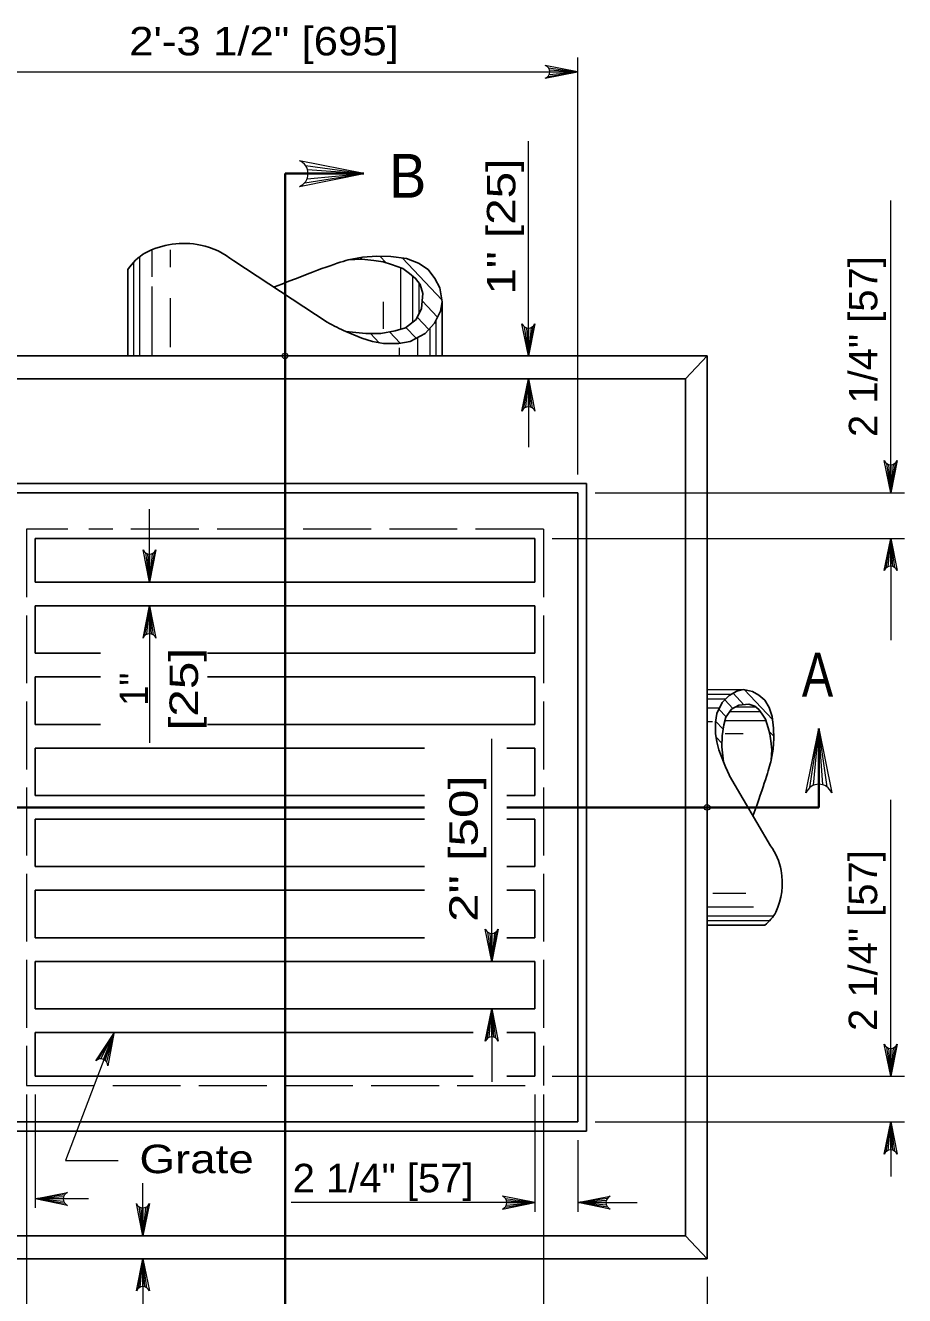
# Model space of a CAD drawing. Extents: x -410.5 to -376.5, y 1617.6 to 1661.6.
# Drawn here: x -393.89 to -389.07, y 1621.21 to 1628.17 of the extents above; entities that cross this region are included whole.
import ezdxf
from ezdxf.enums import TextEntityAlignment as Align

# ---------------------------------------------------------------- set-up
doc = ezdxf.new("R2010")
doc.units = 0
doc.header["$LTSCALE"] = 0.062
doc.header["$PDMODE"] = 32
doc.header["$PDSIZE"] = 0.031
doc.linetypes.add('LONG_DASHED', pattern=[7.5, 6, -1.5])
doc.layers.add('1', color=7, linetype='Continuous', lineweight=13)

msp = doc.modelspace()

# ---------------------------------------------------------------- linework, layer by layer
at = {"layer": '1'}
for p, q in [((-391.02133, 1627.94108), (-390.86108, 1627.91867)), ((-390.85967, 1625.71183), (-390.85967, 1627.99733)), ((-394.07075, 1627.91867), (-392.13725, 1627.91867)), ((-392.13725, 1627.91867), (-390.86108, 1627.91867)), ((-391.02325, 1627.89392), (-390.86108, 1627.91867)), ((-391.01708, 1627.90425), (-390.86108, 1627.91867)), ((-391.01592, 1627.93), (-390.86108, 1627.91867)), ((-391.01425, 1627.91867), (-390.86108, 1627.91867)), ((-391.13075, 1626.3615), (-391.13075, 1627.538)), ((-392.35233, 1627.40575), (-392.03183, 1627.36092)), ((-392.3415, 1627.38358), (-392.03183, 1627.36092)), ((-392.35617, 1627.31133), (-392.03183, 1627.36092)), ((-392.34383, 1627.33217), (-392.03183, 1627.36092)), ((-392.33817, 1627.36092), (-392.03183, 1627.36092)), ((-389.14558, 1625.61192), (-389.14558, 1627.21383)), ((-393.2595, 1626.3615), (-393.2595, 1626.90692)), ((-393.19267, 1626.79592), (-393.19267, 1626.94417)), ((-393.0925, 1626.84867), (-393.0925, 1626.94417)), ((-392.08983, 1626.8895), (-392.09308, 1626.89292)), ((-392.04525, 1626.89225), (-392.05358, 1626.90092)), ((-392.04175, 1626.89217), (-392.05067, 1626.90158)), ((-391.90942, 1626.87167), (-391.94433, 1626.90892)), ((-391.60458, 1626.66892), (-391.82083, 1626.89808)), ((-393.29283, 1626.3615), (-393.29283, 1626.87667)), ((-391.83, 1626.50817), (-391.83, 1626.84417)), ((-391.76325, 1626.54892), (-391.76325, 1626.79842)), ((-391.72983, 1626.59508), (-391.72983, 1626.76183)), ((-393.19267, 1626.3615), (-393.19267, 1626.74308)), ((-393.0925, 1626.40983), (-393.0925, 1626.67908)), ((-391.92458, 1626.51033), (-391.92458, 1626.65842)), ((-391.629, 1626.57508), (-391.71325, 1626.66425)), ((-391.67717, 1626.50608), (-391.741, 1626.57358)), ((-391.63608, 1626.3615), (-391.63608, 1626.56067)), ((-392.12725, 1626.4935), (-392.12867, 1626.49525)), ((-392.113, 1626.48775), (-392.11917, 1626.49417)), ((-391.949, 1626.43408), (-391.9965, 1626.48433)), ((-391.833, 1626.43125), (-391.892, 1626.49367)), ((-391.74558, 1626.4585), (-391.80183, 1626.51817)), ((-391.6695, 1626.3615), (-391.6695, 1626.51467)), ((-391.15317, 1626.52175), (-391.13075, 1626.3615)), ((-391.14208, 1626.51633), (-391.13075, 1626.3615)), ((-391.106, 1626.52367), (-391.13075, 1626.3615)), ((-391.11633, 1626.5175), (-391.13075, 1626.3615)), ((-391.13075, 1626.51467), (-391.13075, 1626.3615)), ((-391.83642, 1626.3615), (-391.83642, 1626.40692)), ((-391.73625, 1626.3615), (-391.73625, 1626.46342)), ((-391.1555, 1626.07442), (-391.13075, 1626.23658)), ((-391.14517, 1626.08058), (-391.13075, 1626.23658)), ((-391.13075, 1626.23658), (-391.13075, 1625.861)), ((-391.13075, 1626.08342), (-391.13075, 1626.23658)), ((-391.11942, 1626.08175), (-391.13075, 1626.23658)), ((-391.10833, 1626.07633), (-391.13075, 1626.23658)), ((-389.168, 1625.77217), (-389.14558, 1625.61192)), ((-389.15692, 1625.76675), (-389.14558, 1625.61192)), ((-389.12075, 1625.77408), (-389.14558, 1625.61192)), ((-389.13117, 1625.76792), (-389.14558, 1625.61192)), ((-389.14558, 1625.76508), (-389.14558, 1625.61192)), ((-390.76525, 1625.61192), (-389.06933, 1625.61192)), ((-393.207, 1625.12225), (-393.207, 1625.522)), ((-391.00125, 1625.36208), (-389.06933, 1625.36208)), ((-389.17033, 1625.19992), (-389.14558, 1625.36208)), ((-389.16, 1625.20608), (-389.14558, 1625.36208)), ((-389.14558, 1625.36208), (-389.14558, 1624.8035)), ((-389.14558, 1625.20892), (-389.14558, 1625.36208)), ((-389.13425, 1625.20725), (-389.14558, 1625.36208)), ((-389.12317, 1625.20183), (-389.14558, 1625.36208)), ((-393.22942, 1625.28242), (-393.207, 1625.12225)), ((-393.21833, 1625.277), (-393.207, 1625.12225)), ((-393.18225, 1625.28433), (-393.207, 1625.12225)), ((-393.19267, 1625.27825), (-393.207, 1625.12225)), ((-393.207, 1625.27542), (-393.207, 1625.12225)), ((-393.23183, 1624.83017), (-393.207, 1624.99225)), ((-393.22142, 1624.83633), (-393.207, 1624.99225)), ((-393.207, 1624.99225), (-393.207, 1624.24208)), ((-393.207, 1624.83917), (-393.207, 1624.99225)), ((-393.19567, 1624.8375), (-393.207, 1624.99225)), ((-393.18458, 1624.83208), (-393.207, 1624.99225)), ((-390.15167, 1624.533), (-389.95292, 1624.533)), ((-389.94633, 1624.53167), (-389.79333, 1624.36975)), ((-390.15167, 1624.508), (-390.01867, 1624.508)), ((-390.15167, 1624.483), (-390.04942, 1624.483)), ((-390.05517, 1624.47725), (-390.01008, 1624.4295)), ((-390.00908, 1624.51333), (-389.9495, 1624.45025)), ((-390.15167, 1624.433), (-390.08358, 1624.433)), ((-390.08683, 1624.426), (-390.047, 1624.38392)), ((-390.0265, 1624.41283), (-389.85992, 1624.41283)), ((-389.99558, 1624.43783), (-389.88425, 1624.43783)), ((-390.15167, 1624.35808), (-390.12142, 1624.35808)), ((-390.10508, 1624.36058), (-390.06342, 1624.31642)), ((-390.05375, 1624.36292), (-389.82933, 1624.36292)), ((-389.58875, 1623.99633), (-389.53917, 1624.32058)), ((-389.568, 1624.00858), (-389.53917, 1624.32058)), ((-389.53917, 1624.01425), (-389.53917, 1624.32058)), ((-389.5165, 1624.011), (-389.53917, 1624.32058)), ((-389.49433, 1624.00008), (-389.53917, 1624.32058)), ((-391.33167, 1623.04342), (-391.33167, 1624.26375)), ((-390.10317, 1624.27375), (-390.06958, 1624.23825)), ((-390.05225, 1624.29208), (-389.95333, 1624.29208)), ((-389.81092, 1624.30342), (-389.78608, 1624.27725)), ((-389.79725, 1624.20433), (-389.791, 1624.19767)), ((-389.79717, 1624.20175), (-389.79133, 1624.1955)), ((-390.06733, 1624.151), (-390.06308, 1624.14642)), ((-390.0635, 1624.14033), (-390.06242, 1624.13925)), ((-389.799, 1624.16833), (-389.79675, 1624.16592)), ((-389.14558, 1622.41375), (-389.14558, 1623.92875)), ((-390.11942, 1623.41775), (-389.93958, 1623.41775)), ((-390.059, 1623.41775), (-389.99525, 1623.41775)), ((-390.15167, 1623.34283), (-389.89675, 1623.34283)), ((-390.09417, 1623.34283), (-389.99525, 1623.34283)), ((-390.15167, 1623.29283), (-389.78733, 1623.29283)), ((-391.35408, 1623.20367), (-391.33167, 1623.04342)), ((-391.30692, 1623.20558), (-391.33167, 1623.04342)), ((-390.15167, 1623.26783), (-389.80758, 1623.26783)), ((-391.343, 1623.19825), (-391.33167, 1623.04342)), ((-391.31725, 1623.19942), (-391.33167, 1623.04342)), ((-391.33167, 1623.19658), (-391.33167, 1623.04342)), ((-391.35642, 1622.62142), (-391.33167, 1622.78358)), ((-391.34608, 1622.62758), (-391.33167, 1622.78358)), ((-391.33167, 1622.78358), (-391.33167, 1622.38375)), ((-391.33167, 1622.63042), (-391.33167, 1622.78358)), ((-391.32033, 1622.62875), (-391.33167, 1622.78358)), ((-391.30925, 1622.62333), (-391.33167, 1622.78358)), ((-393.48625, 1622.50792), (-393.402, 1622.64867)), ((-393.47425, 1622.50967), (-393.402, 1622.64867)), ((-393.45992, 1622.50683), (-393.402, 1622.64867)), ((-393.45, 1622.501), (-393.402, 1622.64867)), ((-393.44183, 1622.49183), (-393.402, 1622.64867)), ((-389.168, 1622.574), (-389.14558, 1622.41375)), ((-389.12075, 1622.57592), (-389.14558, 1622.41375)), ((-389.15692, 1622.56858), (-389.14558, 1622.41375)), ((-389.13117, 1622.56975), (-389.14558, 1622.41375)), ((-389.14558, 1622.56692), (-389.14558, 1622.41375)), ((-391.00125, 1622.41375), (-389.06933, 1622.41375)), ((-393.8805, 1622.31383), (-393.8805, 1620.696)), ((-393.83325, 1622.31383), (-393.83325, 1621.69217)), ((-391.09567, 1622.31383), (-391.09567, 1621.67183)), ((-391.0485, 1622.31383), (-391.0485, 1620.696)), ((-390.76525, 1622.164), (-389.06933, 1622.164)), ((-389.17033, 1622.00183), (-389.14558, 1622.164)), ((-389.16, 1622.008), (-389.14558, 1622.164)), ((-389.14558, 1622.164), (-389.14558, 1621.86558)), ((-389.14558, 1622.01083), (-389.14558, 1622.164)), ((-389.13425, 1622.00917), (-389.14558, 1622.164)), ((-389.12317, 1622.00375), (-389.14558, 1622.164)), ((-390.85967, 1622.06408), (-390.85967, 1621.67192)), ((-393.24325, 1621.53925), (-393.24325, 1621.82733)), ((-393.673, 1621.7645), (-393.83325, 1621.74208)), ((-393.67842, 1621.75342), (-393.83325, 1621.74208)), ((-393.542, 1621.74208), (-393.83325, 1621.74208)), ((-393.68008, 1621.74208), (-393.83325, 1621.74208)), ((-393.67725, 1621.72767), (-393.83325, 1621.74208)), ((-393.67117, 1621.71733), (-393.83325, 1621.74208)), ((-391.25592, 1621.74417), (-391.09567, 1621.72175)), ((-390.69942, 1621.74425), (-390.85967, 1621.72183)), ((-393.26567, 1621.6995), (-393.24325, 1621.53925)), ((-393.25458, 1621.69408), (-393.24325, 1621.53925)), ((-393.2185, 1621.70142), (-393.24325, 1621.53925)), ((-393.22883, 1621.69525), (-393.24325, 1621.53925)), ((-393.24325, 1621.69242), (-393.24325, 1621.53925)), ((-391.09567, 1621.72175), (-392.43067, 1621.72175)), ((-391.25783, 1621.697), (-391.09567, 1621.72175)), ((-391.25167, 1621.70733), (-391.09567, 1621.72175)), ((-391.2505, 1621.73308), (-391.09567, 1621.72175)), ((-391.24883, 1621.72175), (-391.09567, 1621.72175)), ((-390.70483, 1621.73317), (-390.85967, 1621.72183)), ((-390.85967, 1621.72183), (-390.53558, 1621.72183)), ((-390.7065, 1621.72183), (-390.85967, 1621.72183)), ((-390.70367, 1621.70742), (-390.85967, 1621.72183)), ((-390.6975, 1621.69708), (-390.85967, 1621.72183)), ((-393.26808, 1621.25225), (-393.24325, 1621.41433)), ((-393.25767, 1621.25833), (-393.24325, 1621.41433)), ((-393.24325, 1621.41433), (-393.24325, 1620.30867)), ((-393.24325, 1621.26117), (-393.24325, 1621.41433)), ((-393.23192, 1621.2595), (-393.24325, 1621.41433)), ((-393.22083, 1621.25408), (-393.24325, 1621.41433)), ((-390.15167, 1621.31492), (-390.15167, 1620.696))]:
    msp.add_line(p, q, dxfattribs=at)
at = {"layer": '1', "lineweight": 35}
for p, q in [((-392.4645, 1627.36092), (-392.03183, 1627.36092)), ((-392.4645, 1626.28775), (-392.4645, 1627.36092)), ((-392.4645, 1620.41492), (-392.4645, 1626.28775)), ((-389.53917, 1623.88792), (-389.53917, 1624.32058)), ((-395.3405, 1623.88792), (-391.70058, 1623.88792)), ((-391.24825, 1623.88792), (-389.53917, 1623.88792))]:
    msp.add_line(p, q, dxfattribs=at)
at = {"layer": '1', "lineweight": 25}
for p, q in [((-393.32617, 1626.3615), (-393.32617, 1626.83475)), ((-392.234, 1626.54667), (-392.74575, 1626.88208)), ((-391.60275, 1626.3615), (-391.60275, 1626.65917)), ((-390.15167, 1626.3615), (-390.26967, 1626.23658)), ((-390.15167, 1626.3615), (-390.15167, 1625.24567)), ((-394.65925, 1626.23658), (-390.26967, 1626.23658)), ((-390.85967, 1625.61192), (-394.06925, 1625.61192)), ((-390.85967, 1622.164), (-390.85967, 1625.61192)), ((-393.83325, 1625.36208), (-393.83325, 1625.12225)), ((-391.09567, 1625.36208), (-391.09567, 1625.12225)), ((-390.15167, 1625.28292), (-390.15167, 1621.41433)), ((-393.83325, 1625.12225), (-391.09567, 1625.12225)), ((-393.83325, 1624.99225), (-391.09567, 1624.99225)), ((-393.83325, 1624.99225), (-393.83325, 1624.73242)), ((-391.09567, 1624.99225), (-391.09567, 1624.73242)), ((-393.83325, 1624.73242), (-393.47633, 1624.73242)), ((-392.88867, 1624.73242), (-391.09567, 1624.73242)), ((-393.83325, 1624.6025), (-393.83325, 1624.34267)), ((-393.83325, 1624.6025), (-393.47633, 1624.6025)), ((-392.88867, 1624.6025), (-391.09567, 1624.6025)), ((-391.09567, 1624.6025), (-391.09567, 1624.34267)), ((-393.83325, 1624.34267), (-393.47633, 1624.34267)), ((-392.88867, 1624.34267), (-391.09567, 1624.34267)), ((-393.83325, 1624.21275), (-393.83325, 1623.95292)), ((-393.83325, 1624.21275), (-391.70058, 1624.21275)), ((-391.24825, 1624.21275), (-391.09567, 1624.21275)), ((-391.09567, 1624.21275), (-391.09567, 1623.95292)), ((-390.028, 1624.0605), (-389.804, 1623.67742)), ((-393.83325, 1623.95292), (-391.70058, 1623.95292)), ((-391.24825, 1623.95292), (-391.09567, 1623.95292)), ((-393.83325, 1623.56308), (-393.83325, 1623.823)), ((-393.83325, 1623.823), (-391.70058, 1623.823)), ((-391.24825, 1623.823), (-391.09567, 1623.823)), ((-391.09567, 1623.56308), (-391.09567, 1623.823)), ((-393.83325, 1623.56308), (-391.70058, 1623.56308)), ((-391.24825, 1623.56308), (-391.09567, 1623.56308)), ((-393.83325, 1623.43317), (-393.83325, 1623.17333)), ((-393.83325, 1623.43317), (-391.70058, 1623.43317)), ((-391.24825, 1623.43317), (-391.09567, 1623.43317)), ((-391.09567, 1623.17333), (-391.09567, 1623.43317)), ((-390.15167, 1623.24292), (-389.83567, 1623.24292)), ((-393.83325, 1623.17333), (-391.70058, 1623.17333)), ((-391.24825, 1623.17333), (-391.09567, 1623.17333)), ((-393.83325, 1623.04342), (-391.09567, 1623.04342)), ((-393.83325, 1623.04342), (-393.83325, 1622.78358)), ((-391.09567, 1622.78358), (-391.09567, 1623.04342)), ((-393.83325, 1622.78358), (-391.09567, 1622.78358)), ((-393.83325, 1622.65367), (-393.83325, 1622.41375)), ((-393.83325, 1622.65367), (-391.43333, 1622.65367)), ((-391.24825, 1622.65367), (-391.09567, 1622.65367)), ((-391.09567, 1622.41383), (-391.09567, 1622.65367)), ((-393.83325, 1622.41375), (-391.43333, 1622.41383)), ((-391.24825, 1622.41383), (-391.09567, 1622.41383)), ((-394.06925, 1622.16392), (-390.85967, 1622.164)), ((-394.65925, 1621.53925), (-390.26967, 1621.53933)), ((-390.15167, 1621.41433), (-390.26967, 1621.53933)), ((-394.77725, 1621.41433), (-390.15167, 1621.41442))]:
    msp.add_line(p, q, dxfattribs=at)
at = {"layer": '1', "linetype": 'LONG_DASHED'}
for p, q in [((-393.8805, 1625.41208), (-393.8805, 1622.36383)), ((-393.65425, 1625.41208), (-393.8805, 1625.41208)), ((-391.0485, 1625.41208), (-393.54008, 1625.41208)), ((-391.0485, 1625.41208), (-391.0485, 1622.36392)), ((-393.8805, 1622.36383), (-391.0485, 1622.36392))]:
    msp.add_line(p, q, dxfattribs=at)
at = {"layer": '1'}
for points in [[(-391.03808, 1627.88325), (-390.86108, 1627.91867), (-391.03808, 1627.95408)], [(-392.38583, 1627.29008), (-392.03183, 1627.36092), (-392.38583, 1627.43175)], [(-391.09533, 1626.5385), (-391.13075, 1626.3615), (-391.16617, 1626.5385)], [(-391.16617, 1626.05958), (-391.13075, 1626.23658), (-391.09533, 1626.05958)], [(-389.11017, 1625.78892), (-389.14558, 1625.61192), (-389.181, 1625.78892)], [(-389.181, 1625.18508), (-389.14558, 1625.36208), (-389.11017, 1625.18508)], [(-393.17158, 1625.29925), (-393.207, 1625.12225), (-393.24242, 1625.29925)], [(-393.24242, 1624.81525), (-393.207, 1624.99225), (-393.17158, 1624.81525)], [(-389.61, 1623.96658), (-389.53917, 1624.32058), (-389.46833, 1623.96658)], [(-391.29625, 1623.22042), (-391.33167, 1623.04342), (-391.36708, 1623.22042)], [(-391.36708, 1622.60658), (-391.33167, 1622.78358), (-391.29625, 1622.60658)], [(-393.402, 1622.64867), (-393.66692, 1621.95333), (-393.37867, 1621.95333)], [(-393.50167, 1622.49817), (-393.402, 1622.64867), (-393.43608, 1622.47142)], [(-389.11017, 1622.59075), (-389.14558, 1622.41375), (-389.181, 1622.59075)], [(-389.181, 1621.987), (-389.14558, 1622.164), (-389.11017, 1621.987)], [(-393.65625, 1621.70667), (-393.83325, 1621.74208), (-393.65625, 1621.7775)], [(-391.27267, 1621.68633), (-391.09567, 1621.72175), (-391.27267, 1621.75717)], [(-390.68267, 1621.68642), (-390.85967, 1621.72183), (-390.68267, 1621.75725)], [(-393.20783, 1621.71625), (-393.24325, 1621.53925), (-393.27867, 1621.71625)], [(-393.27867, 1621.23733), (-393.24325, 1621.41433), (-393.20783, 1621.23733)]]:
    msp.add_lwpolyline(points, dxfattribs=at)
at = {"layer": '1', "lineweight": 25}
for points in [[(-392.13192, 1626.49558), (-392.04358, 1626.459), (-391.98592, 1626.44083), (-391.92417, 1626.42942), (-391.84142, 1626.42975), (-391.77842, 1626.44142), (-391.69658, 1626.484), (-391.64558, 1626.54192), (-391.61333, 1626.6065), (-391.60275, 1626.65917), (-391.61567, 1626.7345), (-391.64292, 1626.7865), (-391.68025, 1626.83458), (-391.7325, 1626.87092), (-391.7985, 1626.89492), (-391.884, 1626.90692), (-391.96075, 1626.90942), (-392.03933, 1626.90392), (-392.1185, 1626.88775)], [(-392.13192, 1626.49558), (-392.04358, 1626.459), (-391.98592, 1626.44083), (-391.92417, 1626.42942), (-391.84142, 1626.42975), (-391.77842, 1626.44142), (-391.69658, 1626.484), (-391.64558, 1626.54192), (-391.61333, 1626.6065), (-391.60275, 1626.65917), (-391.61567, 1626.7345), (-391.64292, 1626.7865), (-391.68025, 1626.83458), (-391.7325, 1626.87092), (-391.7985, 1626.89492), (-391.884, 1626.90692), (-391.96075, 1626.90942), (-392.03933, 1626.90392), (-392.1185, 1626.88775)], [(-392.1185, 1626.88775), (-392.04392, 1626.89242), (-391.97767, 1626.88542), (-391.92708, 1626.87717), (-391.88158, 1626.86342), (-391.81925, 1626.84008), (-391.78158, 1626.81392), (-391.74908, 1626.7865), (-391.72317, 1626.75342), (-391.71017, 1626.704), (-391.71658, 1626.6215), (-391.74658, 1626.56217), (-391.80492, 1626.51558), (-391.86075, 1626.499), (-391.94008, 1626.48525), (-392.02192, 1626.48392), (-392.13192, 1626.49558)], [(-392.1185, 1626.88775), (-392.04392, 1626.89242), (-391.97767, 1626.88542), (-391.92708, 1626.87717), (-391.88158, 1626.86342), (-391.81925, 1626.84008), (-391.78158, 1626.81392), (-391.74908, 1626.7865), (-391.72317, 1626.75342), (-391.71017, 1626.704), (-391.71658, 1626.6215), (-391.74658, 1626.56217), (-391.80492, 1626.51558), (-391.86075, 1626.499), (-391.94008, 1626.48525), (-392.02192, 1626.48392), (-392.13192, 1626.49558)], [(-394.77725, 1621.41433), (-394.77725, 1626.3615), (-390.15167, 1626.3615)], [(-390.26967, 1626.23658), (-390.26967, 1625.3045), (-390.26967, 1621.53933)], [(-393.83325, 1625.36208), (-393.6495, 1625.36208), (-391.09567, 1625.36208)], [(-390.06217, 1624.13683), (-390.0865, 1624.203), (-390.09867, 1624.24617), (-390.10633, 1624.29233), (-390.10608, 1624.35433), (-390.09825, 1624.4015), (-390.06983, 1624.46275), (-390.03117, 1624.501), (-389.988, 1624.52508), (-389.95292, 1624.533), (-389.9025, 1624.52333), (-389.86783, 1624.50292), (-389.83575, 1624.475), (-389.81142, 1624.43583), (-389.79542, 1624.3865), (-389.78733, 1624.32242), (-389.78575, 1624.265), (-389.78942, 1624.20617), (-389.80017, 1624.14692)], [(-390.06217, 1624.13683), (-390.0865, 1624.203), (-390.09867, 1624.24617), (-390.10633, 1624.29233), (-390.10608, 1624.35433), (-390.09825, 1624.4015), (-390.06983, 1624.46275), (-390.03117, 1624.501), (-389.988, 1624.52508), (-389.95292, 1624.533), (-389.9025, 1624.52333), (-389.86783, 1624.50292), (-389.83575, 1624.475), (-389.81142, 1624.43583), (-389.79542, 1624.3865), (-389.78733, 1624.32242), (-389.78575, 1624.265), (-389.78942, 1624.20617), (-389.80017, 1624.14692)], [(-389.80017, 1624.14692), (-389.79708, 1624.20275), (-389.80175, 1624.25233), (-389.80725, 1624.29017), (-389.8165, 1624.32425), (-389.83208, 1624.37092), (-389.8495, 1624.39917), (-389.86783, 1624.42342), (-389.88992, 1624.44283), (-389.923, 1624.45258), (-389.97808, 1624.44775), (-390.01758, 1624.42533), (-390.04875, 1624.38167), (-390.05983, 1624.33983), (-390.069, 1624.2805), (-390.06992, 1624.21925), (-390.06217, 1624.13683)], [(-389.80017, 1624.14692), (-389.79708, 1624.20275), (-389.80175, 1624.25233), (-389.80725, 1624.29017), (-389.8165, 1624.32425), (-389.83208, 1624.37092), (-389.8495, 1624.39917), (-389.86783, 1624.42342), (-389.88992, 1624.44283), (-389.923, 1624.45258), (-389.97808, 1624.44775), (-390.01758, 1624.42533), (-390.04875, 1624.38167), (-390.05983, 1624.33983), (-390.069, 1624.2805), (-390.06992, 1624.21925), (-390.06217, 1624.13683)]]:
    msp.add_lwpolyline(points, dxfattribs=at)
msp.add_lwpolyline([(-394.1165, 1622.11392), (-390.8125, 1622.114), (-390.8125, 1625.66192), (-394.1165, 1625.66192)], close=True, dxfattribs=at)
at = {"layer": '1'}
for centre, radius, start, end in [((-391.0524, 1627.91873), 0.0382, 292.08605, 67.91218), ((-392.41446, 1627.361), 0.0764, 292.08605, 67.91218), ((-391.13079, 1626.55279), 0.0382, 202.08782, 337.91395), ((-391.13071, 1626.04528), 0.0382, 22.08782, 157.91395), ((-389.1456, 1625.80323), 0.0382, 202.08782, 337.91395), ((-393.20706, 1625.31351), 0.0382, 202.08782, 337.91395), ((-389.14552, 1625.17078), 0.0382, 22.08782, 157.91395), ((-393.20699, 1624.801), 0.0382, 22.08782, 157.91395), ((-389.53909, 1623.938), 0.0764, 22.08782, 157.91395), ((-391.3317, 1623.2347), 0.0382, 202.08782, 337.91395), ((-391.33162, 1622.59227), 0.0382, 22.08782, 157.91395), ((-389.1456, 1622.60507), 0.0382, 202.08782, 337.91395), ((-393.47425, 1622.47151), 0.0382, 359.88795, 135.71407), ((-389.14552, 1621.97271), 0.0382, 22.08782, 157.91395), ((-393.64197, 1621.74214), 0.0382, 112.08782, 247.91395), ((-391.28696, 1621.72181), 0.0382, 292.08605, 67.91218), ((-390.66837, 1621.72189), 0.0382, 112.08782, 247.91395), ((-393.2433, 1621.73057), 0.0382, 202.08782, 337.91395), ((-393.24322, 1621.22306), 0.0382, 22.08782, 157.91395)]:
    msp.add_arc(centre, radius, start, end, dxfattribs=at)
at = {"layer": '1', "lineweight": 25}
for centre, major_axis, start_param, end_param in [((-393.01871, 1626.46973), (0, -0.5089), 2.9497702, 3.6011474), ((-393.01121, 1626.51827), (0, 0.45979), 5.6254463, 6.0881824), ((-393.08821, 1626.65914), (0, 0.30703), 0.5184487, 0.9622613), ((-390.04697, 1623.47864), (0, -0.3251), 1.7657992, 2.2285353), ((-390.07935, 1623.47303), (0, -0.35983), 1.1112416, 1.7626188), ((-389.95285, 1623.42101), (0, -0.21709), 0.608535, 1.0523476)]:
    msp.add_ellipse(centre, major_axis=major_axis, ratio=0.944543, start_param=start_param, end_param=end_param, dxfattribs=at)
for points in [[(-392.1185, 1626.88775), (-392.18733, 1626.869), (-392.29775, 1626.82933), (-392.52242, 1626.73975)], [(-392.234, 1626.54667), (-392.19633, 1626.5265), (-392.16242, 1626.50967), (-392.13192, 1626.49558)], [(-390.028, 1624.0605), (-390.04142, 1624.08867), (-390.05267, 1624.11408), (-390.06217, 1624.13683)], [(-389.80017, 1624.14692), (-389.81275, 1624.09542), (-389.83917, 1624.01267), (-389.899, 1623.8445)]]:
    msp.add_open_spline(points, degree=3, dxfattribs=at)
at = {"layer": '1'}
for p in [(-392.4645, 1626.3615), (-390.15167, 1623.88792)]:
    msp.add_point(p, dxfattribs=at)

# ---------------------------------------------------------------- texts
for s, width, p in [('2\'-3 1/2" [695]', 1.15, (-393.3185, 1628.00892)), ('Grate', 1.2, (-393.26208, 1621.883)), ('2 1/4" [57]', 1.05, (-392.42233, 1621.77825))]:
    msp.add_text(s, height=0.156, dxfattribs=dict(at, width=width)).set_placement(p)
for s, width, p in [('B', 0.95, (-391.79208, 1627.22892)), ('A', 0.8, (-389.54642, 1624.49533))]:
    msp.add_text(s, height=0.24, dxfattribs=dict(at, width=width)).set_placement(p, align=Align.CENTER)
for s, width, p in [('1" [25]', 1.25, (-391.20233, 1627.07038)), ('[25]', 1.3, (-392.94133, 1624.53546)), ('1"', 0.95, (-393.21533, 1624.53546))]:
    msp.add_text(s, height=0.156, rotation=90, dxfattribs=dict(at, width=width)).set_placement(p, align=Align.CENTER)
for s, width, p in [('2 1/4" [57]', 1.05, (-389.21883, 1625.91758)), ('2" [50]', 1.35, (-391.40825, 1623.2595)), ('2 1/4" [57]', 1.05, (-389.21967, 1622.66217))]:
    msp.add_text(s, height=0.156, rotation=90, dxfattribs=dict(at, width=width)).set_placement(p)

doc.saveas('drawing.dxf')
